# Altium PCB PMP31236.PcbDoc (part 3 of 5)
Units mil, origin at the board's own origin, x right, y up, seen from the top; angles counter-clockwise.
Board outline 6425 x 5322.16 mil, 6 copper layers (Top Layer, Power / GND 1, Signal Layer 1, Signal Layer 2, Power / GND 2, Bottom Layer), stack 78.712 mil thick; 732 components, 346 nets, 1735 pads, 719 vias.
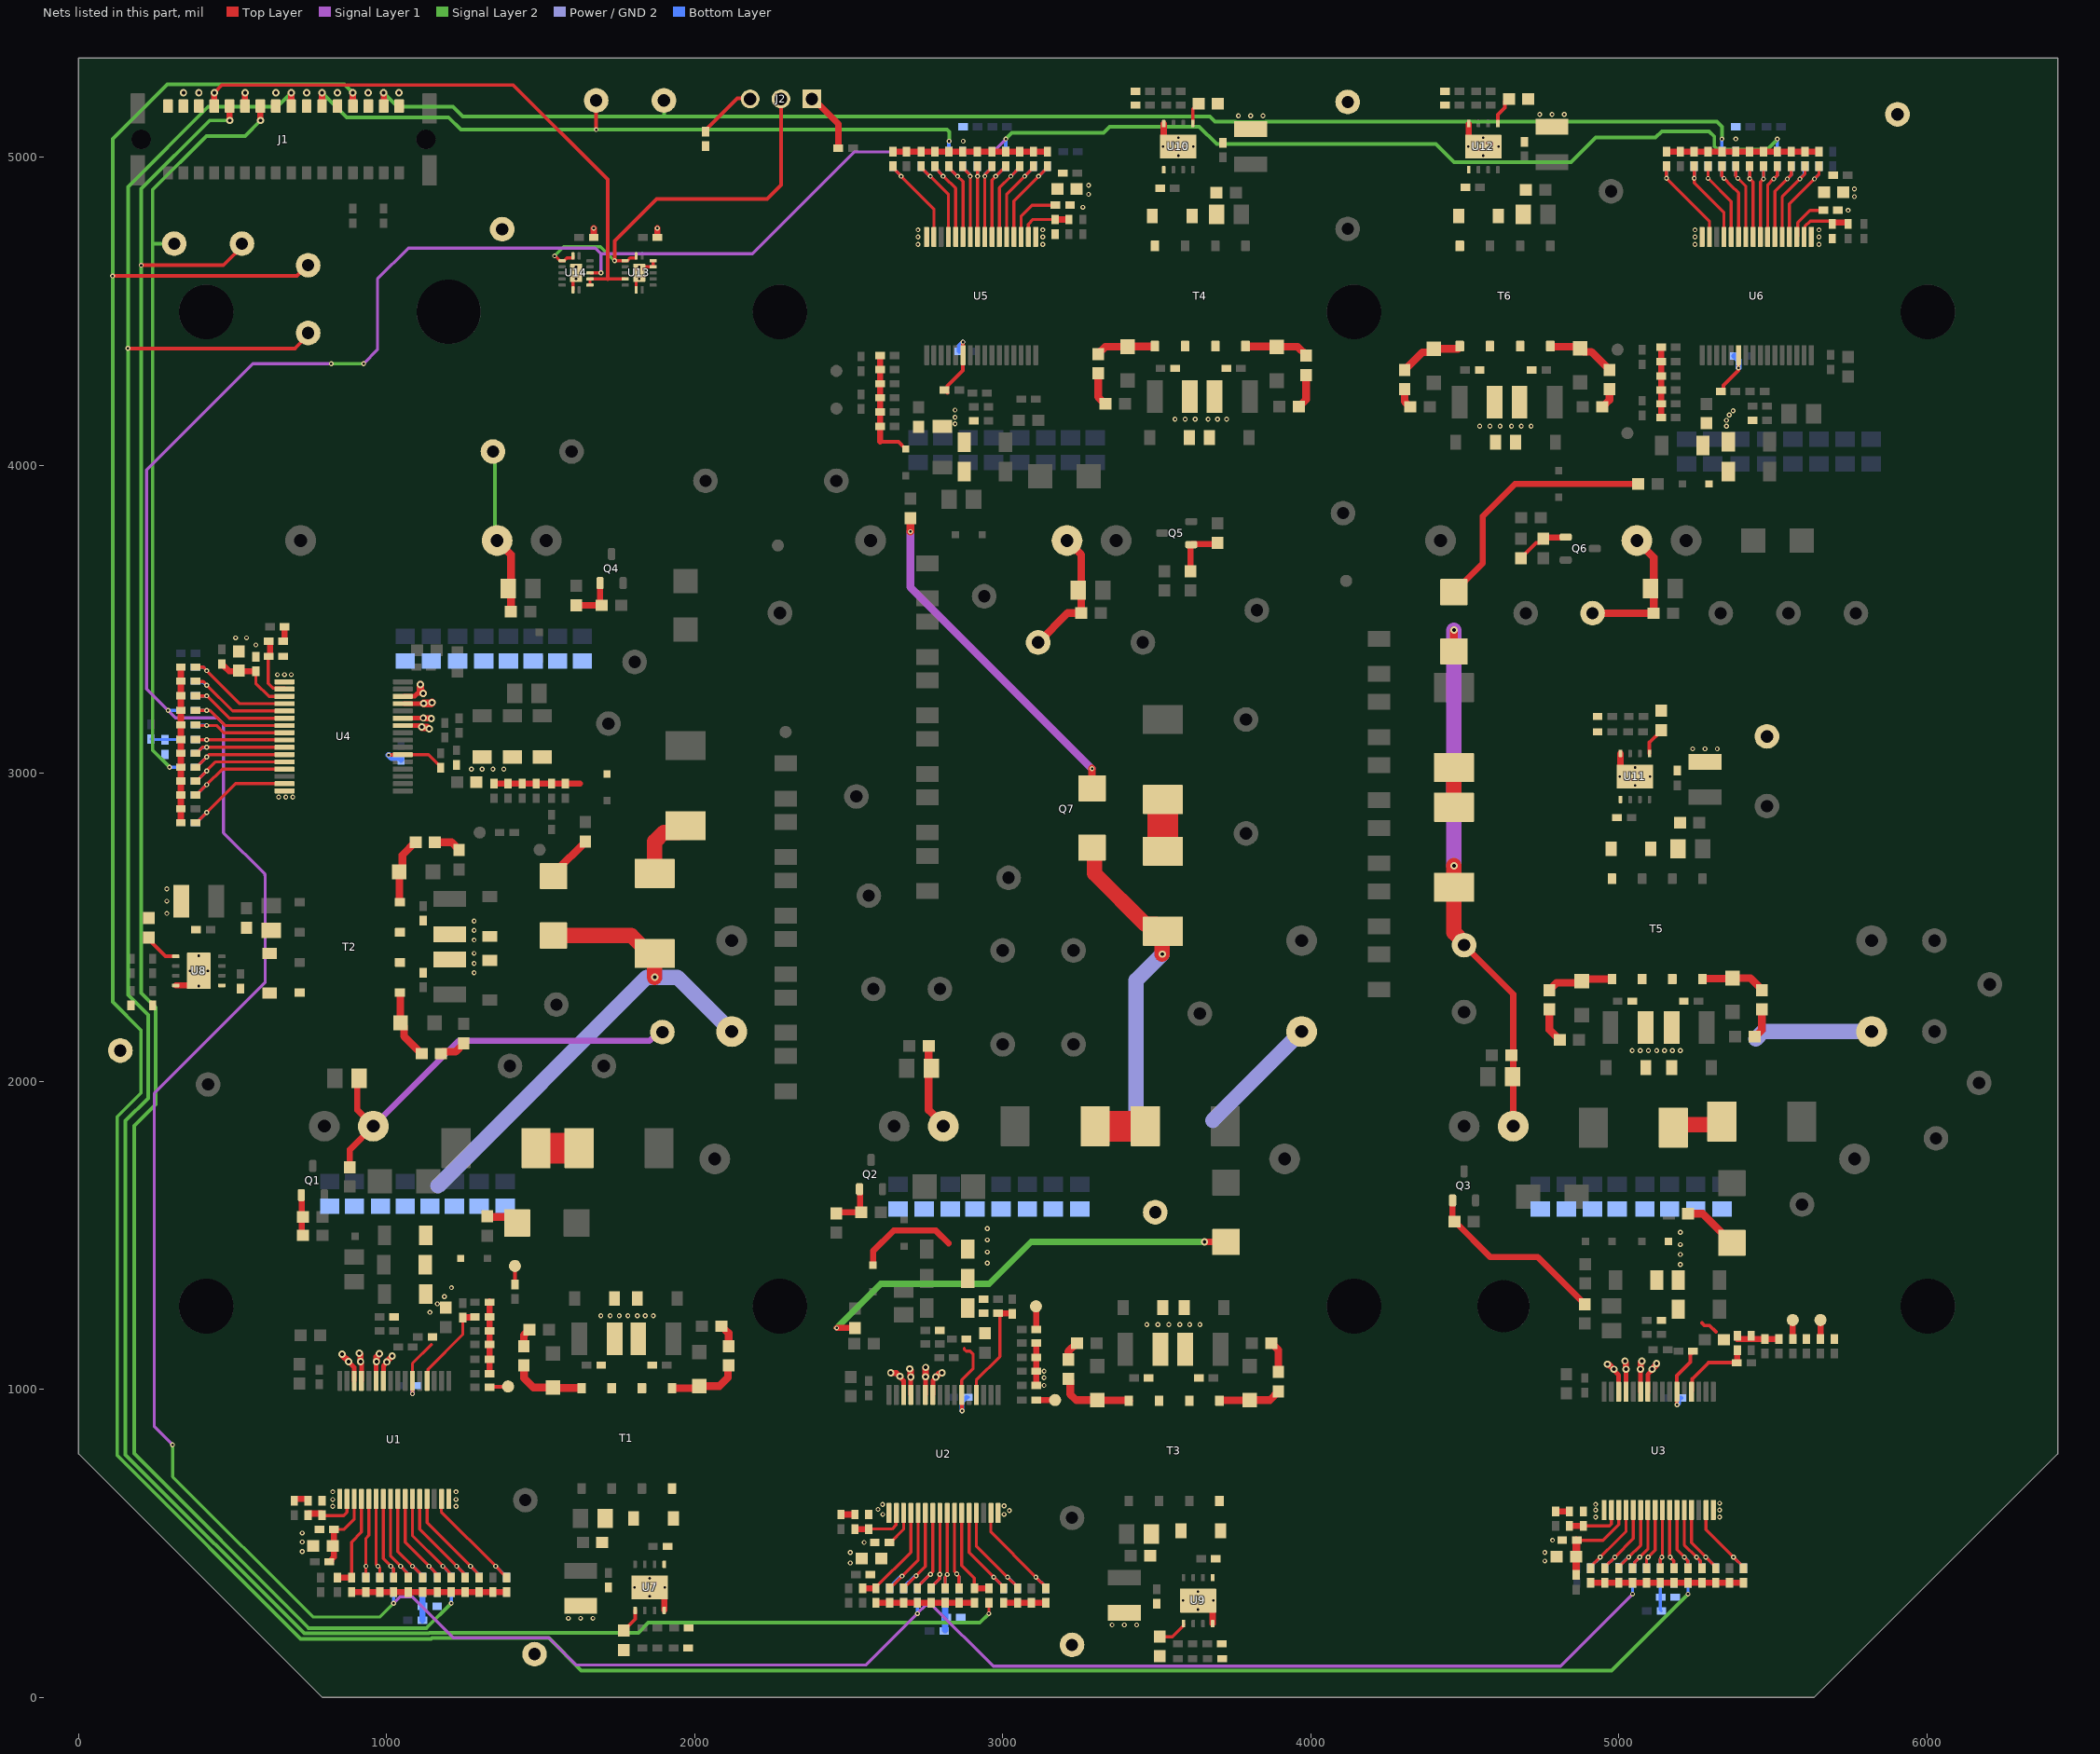
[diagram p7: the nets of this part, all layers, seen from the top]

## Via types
v1: diameter 15.75, hole 7.87, Top Layer to Bottom Layer, tented both sides, 599 vias
v2: diameter 23.62, hole 11.81, Top Layer to Bottom Layer, tented both sides, 92 vias
v3: diameter 19.68, hole 7.87, Top Layer to Bottom Layer, tented both sides, 28 vias

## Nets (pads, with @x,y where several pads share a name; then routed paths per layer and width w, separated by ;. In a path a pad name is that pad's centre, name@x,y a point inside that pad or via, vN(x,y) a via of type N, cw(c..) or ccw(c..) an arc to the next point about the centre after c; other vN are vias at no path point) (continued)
GD2: R18.1 R56.1 R94.1 R130.1 R173.1 R216.1 U14.11 | length 15373.5
  Top Layer w10: U14.11@1660,4625 v1(1695.56,4625)
  Signal Layer 1 w10: v1(304.72,819.93) 245,879.65 245,1960.01 605.35,2320.37 605.35,2667.18 604.33,2668.2 604.33,2672.7 470,2807.03 470,3160 450.04,3179.96 314.45,3179.96 v1(290.22,3204.19) 220,3274.41 220,3985 565,4330 v1(820,4330) ; v1(925,4330) 970,4375 970,4605 1070,4705 1677.67,4705 1695.56,4687.11 ; v1(1022.51,305) 1043.73,326.22 1082.1,326.22 1215.23,193.08 1525.43,193.08 1613.51,105 2556.67,105 v1(2723.05,271.38) 2723.05,272.93 2748.43,298.31 2771.69,298.31 2969.23,100.77 4810.77,100.77 v1(5045,335) ; v1(1695.56,4625) 1695.56,4687.11 ; v1(3010,5060) 2967.85,5017.85 2517.85,5017.85 2187.11,4687.11 1695.56,4687.11
  Signal Layer 2 w10: v1(304.72,819.93) 304.72,716.03 760,260.75 978.26,260.75 v1(1022.51,305) ; v1(820,4330) v1(925,4330)
  Signal Layer 2 w12: v1(3010,5060) 3030,5080 3327.06,5080 3347.06,5100 3637.9,5100 3694.73,5043.17 4405.76,5043.17 4464.82,4984.12 4845.17,4984.12 4925.18,5064.13 5119.13,5064.13 5140,5085 5292.97,5085 5310.5,5067.47 5310.5,5036.55 5321.41,5025.65 5481.66,5025.65 5515,5058.99 v1(5515,5060)
  Bottom Layer w10: v1(290.22,3204.19) 290.37,3204.34 331.23,3204.34 R130.1@331.38,3204.49 ; v1(1022.51,305) R18.1@1022.51,342.13 ; v1(2723.05,271.38) R56.1@2723.05,306.5 ; v1(5045,335) R94.1@5045,371.38 ; R216.1@5515,5018.62 v1(5515,5060)
  Bottom Layer w12: R173.1@3010,5018.62 v1(3010,5060)
GD_WEAK: J1.a4 U13.5 U14.9 U14.10 | length 1915.2
  Top Layer w10: U14.9@1660,4585.63 U14.10@1660,4605.31 1717.22,4605.31 U13.5@1774.45,4605.31
  Top Layer w12: v2(440,5210) 465,5235 1410.56,5235 1717.22,4928.34 1717.22,4605.31
  Top Layer w20: J1.a4@440,5166.54 v2(440,5210)
GND: C1.2 C2.1 C4.1 C5.1 C6.1 C7.1 C15.2 C16.2 C17.2 C18.2 C19.2 C20.2 C21.2 C22.2 C23.2 C31.2 C32.1 C34.1 C35.1 C36.1 C37.1 C45.2 C46.2 C47.2 C48.2 C49.2 C50.2 C51.2 C52.2 C53.2 C61.2 C62.1 C64.1 C65.1 C66.1 C67.1 C75.2 C76.2 C77.2 C78.2 C79.2 C80.2 C81.2 C82.2 C83.2 C91.2 C92.1 C94.1 C95.1 C96.1 C97.1 C105.2 C106.2 C107.2 C108.2 C109.2 C110.2 C111.2 C112.2 C113.2 C121.2 C122.1 C124.1 C125.1 C126.1 C127.1 C135.2 C136.2 C137.2 C138.2 C139.2 C140.2 C141.2 C142.2 C143.2 C151.2 C152.1 C154.1 C155.1 C156.1 C157.1 C165.2 C166.2 C167.2 C168.2 C169.2 C170.2 C171.2 C172.2 C173.2 C184.2 C185.2 C190.2 C194.2 C195.2 C200.2 C204.2 C205.2 C210.2 C214.2 C215.2 C220.2 C224.2 C225.2 C230.2 C234.2 C235.2 C240.2 C241.1 C242.1 J1.a1 J1.a2 J1.a3 J1.a6 J1.a8 J1.a10 J1.a12 J1.a14 J1.a16 R7.1 R30.1 R45.1 R68.1 R83.1 R106.1 R121.1 R144.1 R164.1 R187.1 R207.1 R230.1 R250.1 R251.1 R258.1 R259.1 R266.1 R267.1 R274.1 R275.1 R282.1 R283.1 R290.1 R291.1 R293.1 TP11.1 TP66.1 TP68.1 TP70.1 TP72.1 TP74.1 TP76.1 U1.1 U1.16 U2.1 U2.16 U3.1 U3.16 U4.1 U4.16 U5.1 U5.16 U6.1 U6.16 U7.8 U7.9@1853.72,356.93 U8.8 U8.9@390,2358.62 U9.8 U9.9@3634.37,313.94 U10.8 U10.9@3570,5035 U11.8 U11.9@5052.76,2989.8 U12.8 U12.9@4560.28,5035 U13.7 U13.12 U13.13 U13.15 U14.7 U14.15 | length 3740.6
  Top Layer w10: U14.7@1604.88,4569.88 1604.88,4615.16 U14.15@1614.72,4625 ; U13.7@1809.88,4569.88 1809.88,4600.47 1814.72,4605.31 v3(1819.72,4605.31) ; v3(1819.72,4644.69) U13.12@1865,4644.69 U13.13@1865,4664.37 ; R293.1@2035,5041.38 2035,5037.44 R293.1@2041.81,5030.63 ; v1@2595.23,609.58 v1(2595.23,610) ; v1(2610.61,593.78) v1@2610.61,594.2
  Top Layer w20: U8.8@315.2,2311.38 315.27,2311.45 361.02,2311.45 390,2340.42 U8.9@390,2358.62 ; C107.2@331.38,2840 C105.2@331.38,2975 C94.1@331.38,3020 C95.1@331.38,3065 C112.2@331.38,3251.73 C96.1@331.38,3345 ; J1.a6@540,5166.54 v2(540,5210) ; C6.1@886.06,342.13 1117,342.13 1209.47,342.13 1344.47,342.13 C17.2@1389.47,342.13 ; C242.1@1672.24,4740 v1(1672.24,4770) ; U7.9@1858.72,356.93 U7.9@1876.92,356.93 ; C241.1@1878.62,4740 v1(1878.62,4770) ; U7.8@1900.9,282.19 U7.9@1900.9,327.95 ; C36.1@2588.62,306.38 C52.2@2678.05,306.38 C35.1@2858.05,306.38 C34.1@2908.05,306.38 ; C137.2@2643.15,5018.62 C136.2@2687.76,5018.62 C124.1@2825,5018.62 C125.1@2870,5018.62 C142.2@3055,5018.62 C126.1@3145,5018.62 ; C45.2@3003.05,306.38 C48.2@3048.05,306.38 C46.2@3092.97,306.38 C47.2@3140.22,306.38 ; U10.8@3522.76,5109.8 3522.82,5109.73 3522.82,5063.98 3551.8,5035 U10.9@3570,5035 ; U9.9@3634.37,313.94 3652.57,313.94 3681.55,284.96 3681.55,239.2 U9.8@3681.61,239.13 ; U12.9@4513.03,5036.97 U12.8@4513.03,5109.8 ; C66.1@4908.35,371.38 C81.2@4955,371.38 C82.2@5000,371.38 C83.2@5045,371.38 C79.2@5090,371.38 C80.2@5135,371.38 C75.2@5270,371.38 C78.2@5315,371.38 C76.2@5360,371.38 C77.2@5405,371.38 ; U11.9@5005.58,3018.78 U11.8@5005.58,3064.54 ; C167.2@5155,5018.62 C168.2@5245,5018.62 C154.1@5335,5018.62 C155.1@5380,5018.62 C169.2@5470,5018.62 C171.2@5605,5018.62 C156.1@5650,5018.62
  other v1: 3355,235 3395,235 3435,235 1589.47,256.38 1629.47,256.38 1669.47,256.38 2505,436.03 4760,442.49 2505,469.88 4760,470 725.43,472.93 2550,502.87 725.43,504.17 4785,510 725.43,533.27 4925,585 5327.56,585 3004.61,593.78 3021.63,606.42 4925,608.19 5327.56,608.19 824.92,620 1225,620 3004.61,621.24 2609.98,625.92 4925,626.44 5327.56,630 824.92,642.35 1225,642.35 824.92,667.3 1225,667.3 286.22,2545 286.22,2585 286.22,2625 649.29,2923.07 672.17,2923.07 695,2923.07 5240,3079.54 5280,3079.54 5320,3079.54 645,3320.51 668.07,3320.51 690,3320.51 575,3417.09 509.02,3440 545,3440 2725,4717.8 3130,4717.8 5247.54,4717.8 5650,4717.8 2725,4741.93 3130,4741.93 5247.54,4741.93 5650,4741.93 2725,4765 3130,4765 5247.54,4765 5650,4765 5745,4828.31 3260,4838.13 5765.29,4872.67 3278.79,4880.12 5765.29,4897.83 3278.79,4910 2871.63,5052.54 5380,5060 3765,5134.99 3805,5134.99 3845,5134.99 4743.5,5139.73 4783.5,5139.73 4823.5,5139.73
  other v2: 340,5210 390,5210 640,5210 740,5210 840,5210 940,5210 1040,5210
  other v3: 3634.37,284.8 3585.16,313.94 3683.58,313.94 1853.72,327.8 3634.37,343.07 1804.51,356.93 1902.93,356.93 1853.72,386.06 390,2309.41 360.87,2358.62 419.13,2358.62 390,2407.83 5052.76,2960.67 5003.54,2989.8 5101.97,2989.8 5052.76,3018.94 1614.72,4605.31 1614.72,4644.69 3570,5005.87 4560.28,5005.87 3520.79,5035 3619.21,5035 4511.06,5035 4609.49,5035 3570,5064.13 4560.28,5064.13
GND2H_U: C3.2 C10.2 C11.2 C12.2 C13.2 C14.2 C24.2 C25.2 C28.1 C29.1 C30.1 C182.2 C183.2 C187.1 C188.1 D2.2 D19.1 D22.1 D38.2 D40.1 J15.1 J24.1 Q7.E1 Q7.T2 R25.1 R36.1 R37.1 R38.1 T1.6 T1.7 TP8.1 U1.22 | length 3586.3
  Top Layer w10: U1.22@1083.52,1027.68 1083.52,1083.84 1144.68,1145
  Top Layer w12: v1(1083.52,985.35) U1.22@1083.52,1027.68
  Top Layer w20: R25.1@880.46,1721.44 880.46,1778.3 J15.1@956.69,1854.53 904.65,1906.57 C11.2@904.65,2000 ; R38.1@1333.62,1050.63 C14.2@1333.62,1097.84 C13.2@1333.62,1145.87 R36.1@1333.62,1285
  Top Layer w50: D19.1@1541.56,2473.54 1793.82,2473.54 1852.28,2415.08 D22.1@1870,2415.08 v2(1870,2337.97)
  Signal Layer 1 w20: J15.1@956.69,1854.53 1233.54,2131.37 1853.28,2131.37 1881.91,2160 TP8.1@1895,2160 ; J24.1@2119.27,2160.81 J24.1@2120.08,2161.61
  Power / GND 2 w50: 1166.38,1660.59 1843.76,2337.97 v2(1870,2337.97) 1943.72,2337.97 J24.1@2120.08,2161.61
  Bottom Layer w12: C3.2@1083.52,1015.12 C3.2@1085.25,1016.85
  Bottom Layer w15: v1(1083.52,985.35) C3.2@1083.52,1015.12
  other v1: 1695.18,1238.7 1725.45,1238.7 1755,1238.7 1782.97,1238.7 1813.5,1238.7 1839.51,1238.7 1865.47,1238.7 1140,1250 1164.47,1277.32 1187.34,1301.01 1210.45,1330
GND2H_V: C33.2 C40.2 C41.2 C42.2 C43.2 C44.2 C54.2 C55.2 C58.1 C59.1 C60.1 C202.2 C203.2 C207.1 C208.1 D8.2 D25.1 D28.1 D48.2 D50.1 J10.1 J18.1 Q7.E3 Q7.T4 R63.1 R74.1 R75.1 R76.1 T3.6 T3.7 TP19.1 U2.22 | length 2456.7
  Top Layer w10: U2.22@2867.11,982.05 2867.11,1029.53 2903.74,1066.16 2903.74,1114.6 2894.54,1123.8 2881.81,1123.8 2875,1130.61 2875,1133.03
  Top Layer w12: U2.22@2867.11,982.05 2867.65,981.51 2867.65,930.54 v1(2868.19,930)
  Top Layer w20: D8.2@2578.86,1405.12 2578.86,1448.41 2645.79,1515.35 2783.25,1515.35 2824.43,1474.16 ; R76.1@3108.62,1012.52 R75.1@3108.62,1150
  Top Layer w25: R63.1@2759.55,2115 2759.55,1906.42 2807.09,1858.88 J10.1@2807.09,1854.53
  Top Layer w50: D25.1@3290,2758.54 3298.1,2750.44 3298.1,2674.81 3463.43,2509.49 3497.76,2509.49 D28.1@3520,2487.24 3517.76,2485 v2(3517.76,2412.98)
  Power / GND 2 w50: 3432.46,1905 3432.46,2327.69 v2(3517.76,2412.98) ; 3681.81,1872.95 J18.1@3970.47,2161.61
  Bottom Layer w12: C33.2@2882.58,974.06 C33.2@2886.52,974.06
  Bottom Layer w15: v1(2868.19,930) 2868.19,959.66 C33.2@2882.58,974.06
  other v1: 3134.21,1012.52 3134.21,1037.31 3134.21,1058.84 3467.99,1210 3503.8,1210 3539.38,1210 3575,1210 3607.23,1210 3640.47,1210 2950,1410 2950,1445.83 2950,1485 2950,1521.68
GND2H_W: C63.2 C70.2 C71.2 C72.2 C73.2 C74.2 C84.2 C85.2 C88.1 C89.1 C90.1 C222.2 C223.2 C227.1 C228.1 D14.2 D31.1 D34.1 D58.2 D60.1 J12.1 J19.1 Q7.E5 Q7.T6 R101.1 R112.1 R113.1 R114.1 T5.6 T5.7 TP29.1 U3.22 | length 2561.5
  Top Layer w12: v1(5189.37,949.72) 5189.21,949.88 5189.21,991.89 U3.22@5189.06,992.05 5189.06,1044.97 5232.9,1088.81 5232.9,1112.81 5238.71,1118.62 C85.2@5241.3,1118.62 ; 5270,1215.63 5278.5,1207.13 5294.59,1207.13 5315.19,1186.53 5315.19,1186.05
  Top Layer w20: TP29.1@4498.03,2442.17 4657.48,2282.72 J12.1@4657.48,1854.53 ; C72.2@5385,1163.62 C73.2@5475,1163.62 R113.1@5520,1163.62
  Top Layer w25: D31.1@4465,3395.71 v2(4465,3465)
  Top Layer w50: v2(4465,2699.96) D34.1@4465,2630.08 4465,2483.31 4498.03,2450.28 TP29.1@4498.03,2442.17
  Signal Layer 1 w50: v2(4465,2699.96) v2(4465,3465)
  Power / GND 2 w50: 5444.45,2137 5469.06,2161.61 J19.1@5820.87,2161.61
  Bottom Layer w15: v1(5189.37,949.72) 5189.37,949.93 5194.78,955.34 5194.78,967.91 5199.1,972.22 C63.2@5203.03,972.22
  other v1: 5200.13,1405.36 5200.13,1437.68 5200.22,1470 5200.13,1509.76 5043.62,2100 5070.09,2100 5096.38,2100 5123.31,2100 5148.83,2100 5173.98,2100 5200.13,2100
GND2L_U: C93.2 C100.2 C101.2 C102.2 C103.2 C104.2 C114.2 C115.2 C118.1 C119.1 C120.1 C192.2 C193.2 C197.1 C198.1 D20.2 D43.2 D45.1 J11.1 Q7.E2 R138.1 R149.1 R150.1 R157.1 T2.6 T2.7 TP40.1 U4.22 | length 1061.4
  Top Layer w10: U4.22@1056.93,3060.94 1135.75,3060.94 1175,3021.69 C115.2@1175,3017.76
  Top Layer w12: v1(1006.36,3059.58) 1007.04,3060.26 1051.25,3060.26 U4.22@1051.93,3060.94 U4.22@1056.93,3060.94
  Top Layer w20: C102.2@1348.75,2966.38 C102.2@1348.75,2966.38 1627.46,2966.42 1627.5,2966.46
  Top Layer w25: J11.1@1358.27,3756.1 1403.5,3710.87 R138.1@1403.5,3525
  Signal Layer 2 w12: TP40.1@1345,4045 1351.63,4038.37 1351.63,3762.74 J11.1@1358.27,3756.1
  Bottom Layer w20: v1(1006.36,3059.58) 1015.85,3050.1 1044.92,3050.1 1046.73,3048.29 C93.2@1046.73,3044.35
  other v1: 1283.55,2352.5 1283.55,2382.83 1283.55,2415.49 1283.55,2458.83 1283.55,2490 1283.55,2520.27 1275,3013.7 1310,3013.7 1345,3013.7 1380,3013.7
GND2L_V: C123.2 C130.2 C131.2 C132.2 C133.2 C134.2 C144.2 C145.2 C148.1 C149.1 C150.1 C212.2 C213.2 C217.1 C218.1 D26.2 D53.2 D55.1 J22.1 Q7.E4 R181.1 R192.1 R193.1 R200.1 T4.6 T4.7 TP51.1 U5.22 | length 1036.5
  Top Layer w12: 2601.38,4076.93 2661.38,4076.93 D26.2@2685,4053.31 ; C145.2@2811.38,4245 C145.2@2815.32,4245 ; C145.2@2821.13,4235.25 2821.13,4239.19 C145.2@2815.32,4245 ; v1(2870.94,4400.39) U5.22@2870.94,4358.07 2870.94,4307.59 2821.13,4257.77 2821.13,4250.81 C145.2@2815.32,4245
  Top Layer w20: 2601.38,4076.93 R200.1@2601.38,4126.93 R192.1@2601.38,4220 R193.1@2601.38,4356.5
  Top Layer w25: TP51.1@3115.04,3425 3210.94,3520.91 R181.1@3254.78,3520.91 3254.78,3709.98 J22.1@3208.66,3756.1
  Bottom Layer w15: C123.2@2859.09,4370.02 2859.09,4388.53 v1(2870.94,4400.39)
  other v1: 2845,4135 3559.25,4150 3592.28,4150 3624.92,4150 3666.75,4150 3697.17,4150 3727.05,4150 2845,4156.46 2845,4179.65
GND2L_W: C153.2 C160.2 C161.2 C162.2 C163.2 C164.2 C174.2 C175.2 C178.1 C179.1 C180.1 C232.2 C233.2 C237.1 C238.1 D32.2 D63.2 D65.1 J7.1 Q7.E6 R224.1 R235.1 R236.1 R243.1 T6.6 T6.7 TP62.1 U6.22 | length 874.7
  Top Layer w10: C175.2@5331.69,4240 5333.53,4240 C175.2@5340.34,4246.81
  Top Layer w12: C175.2@5340.34,4246.81 5340.34,4260.13 5388.06,4307.85 5388.06,4316.09 v1(5388.78,4316.81) ; v1@5388.94,4316.81 U6.22@5388.94,4358.07
  Top Layer w20: C162.2@5137.87,4155 C163.2@5137.87,4290.19 C164.2@5137.87,4337.19 R236.1@5137.87,4384.06
  Top Layer w25: TP62.1@4915,3520 R224.1@5113.5,3520 5113.5,3701.65 J7.1@5059.06,3756.1
  Bottom Layer w20: C153.2@5376.2,4355 5380.14,4355 5381.95,4353.19 5381.95,4349.25 5388.78,4342.42 v1(5388.78,4316.81)
  other v1: 4548.62,4127.47 4581.97,4127.47 4615,4127.47 4651.79,4127.47 4683.5,4127.47 4715.47,4127.47 5350,4127.47 5350,4146.46 5358.96,4163.63 5371.32,4177.26
HS_DO_PWM_U: J1.a5 R5.1 TP5.1 | length 6280.8
  Top Layer w12: v1(202.99,4650) 470,4650 TP5.1@540,4720
  Top Layer w20: v2(490,5120) J1.a5@490,5166.54
  Signal Layer 2 w12: v2(490,5120) 425,5120 202.99,4897.99 v1(202.99,4650) 202.99,2287.01 250,2240 250,1925 180,1855 180,791.5 746.5,225 1129.47,225 v1(1209.47,305)
  Bottom Layer w10: v1(1209.47,305) R5.1@1209.47,342.13
HS_DO_PWM_V: J1.a9 R43.1 TP16.1 | length 8592.3
  Top Layer w10: v1(2955,271.38) R43.1@2955,306.38
  Top Layer w12: v1(160,4380) 701.54,4380 TP16.1@751.54,4430
  Top Layer w20: J1.a9@690,5166.54 v2(690,5210)
  Signal Layer 2 w12: v2(690,5210) 645,5165 420,5165 160,4905 v1(160,4380) 160,2280 225,2215 225,1945 151.57,1871.57 151.57,787.61 732.09,207.09 1136.89,207.09 1139.6,209.81 1817.03,209.81 1849.34,242.13 2925.75,242.13 v1(2955,271.38)
HS_DO_PWM_W: J1.a13 R81.1 TP26.1 | length 11433.2
  Top Layer w12: v1(110,4615) 707.92,4615 TP26.1@742.92,4650
  Top Layer w20: v2(889.84,5210) 889.92,5209.92 889.92,5166.61 J1.a13@890,5166.54
  Signal Layer 1 w12: TP26.1@742.92,4650 TP26.1@745,4650
  Signal Layer 2 w12: v2(889.84,5210) 862.42,5237.42 287.42,5237.42 110,5060 v1(110,4615) 110,2257.85 202.09,2165.76 202.09,1962.09 125,1885 125,785 720.81,189.19 1144.3,189.19 1147.02,191.91 1526.61,191.91 1631.4,87.11 4977.11,87.11 v1(5225,335)
  Bottom Layer w10: v1(5225,335) R81.1@5225,371.38
LS_DO_PWM_U: J1.a7 R119.1 TP36.1 | length 2498.9
  Top Layer w20: v2(590,5120) J1.a7@590,5166.54
  Signal Layer 2 w12: 240,4720 TP36.1@315,4720 ; v1(295,3020) 240,3075 240,4895 415,5070 540,5070 v2(590,5120)
  Bottom Layer w10: v1(295,3020) R119.1@331.38,3020
LS_DO_PWM_V: J1.a11 R162.1 TP47.1 | length 2291.8
  Top Layer w12: v1(1680,5090.22) TP47.1@1680,5185
  Top Layer w20: J1.a11@790,5166.54 v2(790,5210)
  Signal Layer 2 w12: v2(790,5210) 870,5130 1200.79,5130 1240.57,5090.22 2818.85,5090.22 2826.16,5082.91 v1(2826.16,5052.54)
  Bottom Layer w12: R162.1@2825,5018.62 2825.58,5019.2 2825.58,5051.96 v1(2826.16,5052.54)
LS_DO_PWM_W: J1.a15 R205.1 TP58.1 | length 4568.3
  Top Layer w20: J1.a15@990,5166.54 v2(990,5210)
  Signal Layer 2 w12: v2(990,5210) 1035,5165 1215,5165 1247.5,5132.5 1900,5132.5 ; TP58.1@1900,5185 1900,5132.5 ; v1(5335,5060) 5335,5100 5319.29,5115.71 3853.69,5115.71 3853.19,5115.21 3756.81,5115.21 3756.31,5115.71 3689.07,5115.71 3672.27,5132.5 1900,5132.5
  Bottom Layer w10: R205.1@5335,5018.62 v1(5335,5060)
NetC1_1: C1.1 C2.2 R1.2 U1.3 | length 258
  Top Layer w10: C2.2@828.62,545 860,545 894.55,579.55 U1.3@894.55,643.82
  Top Layer w20: R1.2@813.62,440 817.56,440 819.37,441.81 819.37,445.75 828.62,455 C2.2@828.62,545
NetC4_2: C4.2 R5.2 U1.11 | length 356.3
  Top Layer w10: U1.11@1083.52,643.82 1083.52,524.25 v1(1182.09,425.68) C4.2@1214.47,393.31 ; C4.2@1209.47,389.37 C4.2@1209.47,393.31
  Bottom Layer w10: v1(1182.09,425.68) 1202.66,405.12 1202.66,396.18 R5.2@1209.47,389.37
NetC5_2: C5.2 R7.2 U1.10 | length 347.5
  Top Layer w10: U1.10@1059.9,643.82 1059.9,502.87 v1(1137.09,425.68) C5.2@1169.47,393.31 ; C5.2@1164.47,389.37 C5.2@1164.47,393.31
  Bottom Layer w10: v1(1137.09,425.68) 1157.66,405.12 1157.66,396.18 R7.2@1164.47,389.37
NetC6_2: C6.2 R8.2 U1.4 | length 313.8
  Top Layer w10: C6.2@886.06,389.37 886.06,504.17 918.17,536.29 U1.4@918.17,643.82
  Top Layer w20: R8.2@840,388.62 C6.2@886.06,388.62
NetC7_2: C7.2 R11.2 U1.2 | length 176
  Top Layer w10: C7.2@790,596.38 796.38,590 860,590 870.93,600.93 U1.2@870.93,643.82
  Top Layer w20: R11.2@745,596.38 C7.2@790,596.38
NetC12_1: C12.1 R33.1 U1.20 | length 293.5
  Top Layer w10: U1.20@1130.77,1027.68 1133.84,1030.75 1133.84,1064.74 1246.68,1177.58 R33.1@1246.68,1232.34 R33.1@1248.01,1233.67
  Top Layer w20: R33.1@1248.01,1233.67 1285.05,1233.67 C12.1@1286.38,1235
NetC15_1: C15.1 R28.2 U1.12 | length 365.2
  Top Layer w10: U1.12@1107.15,643.82 1107.15,545.63 v1(1227.09,425.68) C15.1@1259.47,393.31 ; C15.1@1254.47,389.37 C15.1@1254.47,393.31
  Bottom Layer w10: v1(1227.09,425.68) 1247.66,405.12 1247.66,396.18 R28.2@1254.47,389.37
NetC17_1: C17.1 R34.2 U1.15 | length 400.9
  Top Layer w10: U1.15@1178.01,643.82 1177.15,642.95 1177.15,602.32 v1(1353.79,425.68) C17.1@1384.41,395.06 ; C17.1@1382.66,400.12 1389.47,393.31 C17.1@1389.47,389.37
  Bottom Layer w10: v1(1353.79,425.68) 1379.35,400.12 1382.66,400.12 1389.47,393.31 R34.2@1389.47,390
NetC18_1: C18.1 R35.2 U1.13 | length 374.1
  Top Layer w10: U1.13@1130.77,643.82 1130.77,567.01 v1(1272.09,425.68) C18.1@1304.47,393.31 ; C18.1@1299.47,389.37 C18.1@1299.47,393.31
  Bottom Layer w10: v1(1272.09,425.68) 1292.66,405.12 1292.66,396.18 R35.2@1299.47,389.37
NetC19_1: C19.1 R22.2 U1.8 | length 331.7
  Top Layer w10: U1.8@1012.66,643.82 1012.66,458.03 v1(1045,425.68) 1067.94,402.74 C19.1@1067.94,391.18 ; C19.1@1062.94,396.18 C19.1@1067.94,391.18 ; C19.1@1069.76,389.37 C19.1@1067.94,391.18
  Bottom Layer w10: v1(1045,425.68) 1062.94,407.74 1062.94,396.18 R22.2@1069.76,389.37
NetC20_1: C20.1 R26.2 U1.9 | length 339.4
  Top Layer w10: U1.9@1036.28,643.82 1036.28,472.93 v1(1083.52,425.68) 1084.62,425.68 1117,393.31 C20.1@1117,389.37
  Bottom Layer w10: v1(1083.52,425.68) 1084.62,425.68 1117,393.31 R26.2@1117,389.37
NetC21_1: C21.1 R14.2 U1.5 | length 294.6
  Top Layer w10: C21.1@932.51,389.37 v1(932.51,425.68) 932.51,516.34 941.79,525.62 U1.5@941.79,643.82
  Bottom Layer w10: R14.2@932.51,389.37 v1(932.51,425.68)
NetC22_1: C22.1 R15.2 U1.6 | length 298.3
  Top Layer w10: U1.6@965.41,643.82 965.41,431.73 v1(971.46,425.68) 977.51,419.63 C22.1@977.51,389.37
  Bottom Layer w10: v1(971.46,425.68) 971.46,424.13 977.51,418.08 R15.2@977.51,389.37
NetC23_1: C23.1 R18.2 U1.7 | length 308.4
  Top Layer w10: U1.7@989.04,643.82 989.04,450 v1(1013.35,425.68) 1022.51,416.52 C23.1@1022.51,389.37
  Bottom Layer w10: v1(1013.35,425.68) 1022.51,416.52 R18.2@1022.51,389.37
NetC31_1: C31.1 C32.2 R39.2 U2.3 | length 113.1
  Top Layer w10: C32.2@2635.73,502.68 2678.13,545.08 U2.3@2678.13,598.19
NetC34_2: C34.2 R43.2 U2.11 | length 312.3
  Top Layer w10: U2.11@2867.11,598.19 2867.11,427.8 2908.05,386.85 2908.05,353.74 C34.2@2908.17,353.62 ; R43.2@2955,353.62 R43.2@2955,357.56
  Top Layer w20: C34.2@2908.17,353.62 R43.2@2955,353.62
NetC35_2: C35.2 R45.2 U2.10 | length 300.7
  Top Layer w10: U2.10@2843.49,598.19 2843.49,408.11 2858.05,393.54 C35.2@2858.05,353.62
  Bottom Layer w10: v1(2850.77,400.83) 2850.77,399.27 2858.05,391.99 R45.2@2858.05,353.74
NetC36_2: C36.2 R46.2 U2.4 | length 335
  Top Layer w10: C36.2@2588.62,353.62 2588.62,357.56 2701.75,470.69 U2.4@2701.75,598.19
  Top Layer w20: R46.2@2545,353.62 C36.2@2588.62,353.62
NetC37_2: C37.2 R49.2 U2.2 | length 193.2
  Top Layer w10: 2550,546.38 2640.62,546.38 2653.15,558.91 2653.15,596.83 U2.2@2654.51,598.19
  Top Layer w20: R49.2@2520,546.38 C37.2@2565,546.38
NetC42_1: C42.1 R71.1 U2.20 | length 343.1
  Top Layer w10: U2.20@2914.35,982.05 2914.35,1029.53 2991.2,1106.38 2991.2,1240.77 C42.1@2985.87,1246.11
  Top Layer w20: C42.1@2985.87,1246.11 3029.98,1246.11 R71.1@3030.63,1245.45
NetC45_1: C45.1 R66.2 U2.12 | length 340.7
  Top Layer w10: U2.12@2890.73,598.19 2890.73,469.88 v1(2970.75,389.86) 3003.05,357.56 C45.1@3003.05,353.62
  Bottom Layer w10: v1(2970.75,389.86) 2970.87,389.86 3003.05,357.68 R66.2@3003.05,353.74
NetC47_1: C47.1 R72.2 U2.15 | length 368
  Top Layer w10: U2.15@2961.6,598.19 2961.6,536.18 v1(3107.91,389.86) 3140.22,357.56 C47.1@3140.22,353.74
  Bottom Layer w10: v1(3107.91,389.86) 3108.03,389.86 3140.22,357.68 R72.2@3140.22,353.74
NetC48_1: C48.1 R73.2 U2.13 | length 349.5
  Top Layer w10: U2.13@2914.35,598.19 2914.35,491.26 v1(3015.75,389.86) 3048.05,357.56 C48.1@3048.05,353.62
  Bottom Layer w10: v1(3015.75,389.86) 3015.87,389.86 3048.05,357.68 R73.2@3048.05,353.74
NetC49_1: C49.1 R60.2 U2.8 | length 307.8
  Top Layer w10: C49.1@2768.56,358.07 2794.55,384.05 2794.55,397.68 v1(2795.65,398.78) ; v1@2796.24,398.78 U2.8@2796.24,598.19
  Bottom Layer w10: R60.2@2768.05,353.74 2768.05,357.68 2794.55,384.17 2794.55,397.68 v1(2795.65,398.78)
NetC50_1: C50.1 R64.2 U2.9 | length 294.9
  Top Layer w10: C50.1@2813.05,353.74 2813.05,390.18 2819.86,396.99 v1(2819.86,398.54) U2.9@2819.86,598.19
  Bottom Layer w10: R64.2@2813.05,353.74 2813.05,390.18 2819.86,396.99 v1(2819.86,398.54)
NetC51_1: C51.1 R52.2 U2.5 | length 343.8
  Top Layer w10: C51.1@2633.05,353.62 2633.05,357.56 2639.86,364.37 2643.8,364.37 v1(2672.97,393.54) 2725.37,445.94 U2.5@2725.37,598.19
  Bottom Layer w10: R52.2@2633.05,353.74 2633.05,357.68 2667.82,392.44 2671.87,392.44 v1(2672.97,393.54)
NetC52_1: C52.1 R53.2 U2.6 | length 336.1
  Top Layer w10: C52.1@2678.05,353.74 2678.05,357.56 2684.86,364.37 2688.68,364.37 v1(2718.84,394.53) 2749,424.68 U2.6@2749,598.19
  Bottom Layer w10: R53.2@2678.05,353.74 2678.05,357.68 2713.8,393.43 2717.74,393.43 v1(2718.84,394.53)
NetC53_1: C53.1 R56.2 U2.7 | length 324.7
  Top Layer w10: C53.1@2723.05,357.56 2764.28,398.78 v1(2765.11,398.78) 2765.11,400.34 2772.62,407.85 U2.7@2772.62,598.19
  Bottom Layer w10: R56.2@2723.05,353.74 2723.05,357.68 2764.16,398.78 v1(2765.11,398.78)
NetC61_1: C61.1 C62.2 R77.2 U3.3 | length 316.1
  Top Layer w10: C62.2@4864.27,509.35 4948.72,509.35 5000.08,560.71 U3.3@5000.08,608.19
  Top Layer w25: R77.2@4861.5,396.97 C61.1@4861.5,456.81 ; C61.1@4862.28,457.6 C62.2@4862.28,509.31
NetC64_2: C64.2 R81.2 U3.11 | length 245.8
  Top Layer w10: U3.11@5189.06,608.19 5189.06,478.94 v1(5213,455) 5224.49,443.51 5224.49,419.13 C64.2@5225,418.62
  Bottom Layer w10: v1(5213,455) 5223.79,444.21 5223.79,419.83 R81.2@5225,418.62
NetC65_2: C65.2 R83.2 U3.10 | length 237.3
  Top Layer w10: U3.10@5165.43,608.19 5165.43,456.81 v1(5167.24,455) 5178.73,443.51 5178.73,419.89 C65.2@5180,418.62
  Bottom Layer w10: v1(5167.24,455) 5178.03,444.21 5178.03,420.59 R83.2@5180,418.62
NetC66_2: C66.2 R84.2 U3.4 | length 286.8
  Top Layer w10: C66.2@4908.35,418.62 4908.35,422.56 5023.7,537.91 U3.4@5023.7,608.19
  Bottom Layer w10: R84.2@4908.35,418.62 4908.35,422.56 4940,454.21 v1(4940,455)
NetC67_2: C67.2 R87.2 U3.2 | length 184.8
  Top Layer w10: C67.2@4885,556.38 4970.6,556.4 4976.46,562.26 U3.2@4976.46,608.19
  Top Layer w20: R87.2@4840,556.38 C67.2@4885,556.38
NetC72_1: C72.1 R109.1 U3.20 | length 244.8
  Top Layer w12: U3.20@5236.3,992.05 5238.37,994.12 5238.37,1033.14 5292.23,1087 R109.1@5384.2,1087
  Top Layer w20: R109.1@5384.2,1087 5384.2,1120.58 C72.1@5385,1121.38
NetC75_1: C75.1 R104.2 U3.12 | length 256.9
  Top Layer w10: U3.12@5212.68,608.19 5212.68,494.92 v1(5252.6,455) 5265.1,442.49 5265.1,423.52 C75.1@5270,418.62
  Bottom Layer w10: v1(5252.6,455) 5263.38,444.21 5263.38,425.24 R104.2@5270,418.62
NetC77_1: C77.1 R110.2 U3.15 | length 289.7
  Top Layer w10: U3.15@5283.54,608.19 5283.54,544.02 v1(5372.56,455) 5405,422.56 C77.1@5405,418.62
  Bottom Layer w10: v1(5372.56,455) 5405,422.56 R110.2@5405,418.62
NetC78_1: C78.1 R111.2 U3.13 | length 272
  Top Layer w10: U3.13@5236.3,608.19 5236.3,501.26 v1(5282.56,455) 5315,422.56 C78.1@5315,418.62
  Bottom Layer w10: v1(5282.56,455) 5315,422.56 R111.2@5315,418.62
NetC79_1: C79.1 R98.2 U3.8 | length 240
  Top Layer w10: C79.1@5090,418.62 5090,449.37 v1(5095.63,455) 5118.19,477.56 U3.8@5118.19,608.19
  Bottom Layer w10: R98.2@5090,418.62 5090,447.81 5095.63,453.44 v1(5095.63,455)
NetC80_1: C80.1 R102.2 U3.9 | length 230.8
  Top Layer w10: C80.1@5135,418.62 5135,450 v1(5140,455) 5141.81,456.81 U3.9@5141.81,608.19
  Bottom Layer w10: R102.2@5135,418.62 5135,448.44 5140,453.44 v1(5140,455)
NetC81_1: C81.1 R90.2 U3.5 | length 277.6
  Top Layer w10: C81.1@4955,418.62 4955,422.56 v1(4987.44,455) 5047.32,514.88 U3.5@5047.32,608.19
  Bottom Layer w10: R90.2@4955,418.62 4955,422.56 v1(4987.44,455)
NetC82_1: C82.1 R91.2 U3.6 | length 268
  Top Layer w10: C82.1@5000,418.62 5000,422.56 v1(5032.44,455) 5070.94,493.5 U3.6@5070.94,608.19
  Bottom Layer w10: R91.2@5000,420.59 5000,424.53 5029.37,453.9 5031.34,453.9 v1(5032.44,455)
NetC83_1: C83.1 R94.2 U3.7 | length 256.1
  Top Layer w10: C83.1@5045,418.62 5051.81,425.43 5051.81,438.46 v1(5068.35,455) 5094.57,481.22 U3.7@5094.57,608.19
  Bottom Layer w10: R94.2@5045,418.62 5051.81,425.43 5051.81,438.46 v1(5068.35,455)
NetC91_1: C91.1 C92.2 R115.2 U4.3 | length 276.8
  Top Layer w10: C92.2@575,3331.38 575,3292.57 617.65,3249.92 U4.3@673.07,3249.92
  Top Layer w20: R115.2@464.8,3355 464.8,3351.06 466.61,3349.25 470.55,3349.25 488.43,3331.38 C92.2@575,3331.38
NetC94_2: C94.2 R119.2 U4.11 | length 362.2
  Top Layer w10: C94.2@378.62,3020 382.56,3020 v1(415.71,3053.15) 423.5,3060.94 U4.11@673.07,3060.94
  Bottom Layer w10: R119.2@378.62,3020 382.56,3020 v1(415.71,3053.15)
NetC95_2: C95.2 R121.2 U4.10 | length 347.7
  Top Layer w10: C95.2@378.62,3065 382.56,3065 402.13,3084.57 v1(415.71,3084.57) U4.10@673.07,3084.57
  Bottom Layer w10: R121.2@378.62,3065 382.56,3065 401.03,3083.47 414.61,3083.47 v1(415.71,3084.57)
NetC96_2: C96.2 R122.2 U4.4 | length 385.5
  Top Layer w10: C96.2@378.62,3345 404.21,3345 v1(415.71,3333.5) 522.91,3226.3 U4.4@673.07,3226.3
  Bottom Layer w10: R122.2@378.62,3345 404.21,3345 v1(415.71,3333.5)
NetC97_2: C97.2 R125.2 U4.2 | length 195.7
  Top Layer w10: C97.2@614.8,3373.35 614.8,3292.57 630.76,3276.61 670,3276.61 U4.2@673.07,3273.54
  Top Layer w20: C97.2@621.38,3380 R125.2@621.38,3428.82
NetC105_1: C105.1 R142.2 U4.12 | length 371
  Top Layer w10: C105.1@378.62,2975 382.56,2975 444.88,3037.32 U4.12@673.07,3037.32
  Bottom Layer w10: R142.2@378.62,2975 382.56,2975 415.42,3007.86 v1(415.71,3007.86)
NetC107_1: C107.1 R147.2 U4.15 | length 397.6
  Top Layer w10: C107.1@378.62,2840 382.56,2840 v1(415.71,2873.15) 509.02,2966.46 U4.15@673.07,2966.46
  Bottom Layer w10: R147.2@378.62,2840 382.56,2840 v1(415.71,2873.15)
NetC108_1: C108.1 R148.2 U4.13 | length 379.9
  Top Layer w10: C108.1@378.62,2930 382.56,2930 v1(415.71,2963.15) 466.26,3013.7 U4.13@673.07,3013.7
  Bottom Layer w10: R148.2@378.62,2930 382.56,2930 v1(415.71,2963.15)
NetC109_1: C109.1 R134.2 U4.8 | length 342.8
  Top Layer w10: C109.1@378.62,3157.24 380.43,3155.43 v1(415.71,3155.43) 447.09,3155.43 470.71,3131.81 U4.8@673.07,3131.81
  Bottom Layer w10: R134.2@378.62,3157.24 379.53,3156.34 414.8,3156.34 v1(415.71,3155.43)
NetC110_1: C110.1 R140.2 U4.9 | length 332.7
  Top Layer w10: C110.1@378.62,3110 379.53,3109.09 v1(415.71,3109.09) 672.17,3109.09 U4.9@673.07,3108.19
  Bottom Layer w10: R140.2@378.62,3110 379.07,3109.55 415.26,3109.55 v1(415.71,3109.09)
NetC111_1: C111.1 R128.2 U4.5 | length 377.5
  Top Layer w10: C111.1@378.62,3300 380.71,3297.91 404.21,3297.91 v1(415.71,3286.42) 499.45,3202.68 U4.5@673.07,3202.68
  Bottom Layer w10: R128.2@378.62,3300 381.56,3297.06 403.51,3297.06 414.15,3286.42 v1(415.71,3286.42)
NetC112_1: C112.1 R129.2 U4.6 | length 361.6
  Top Layer w10: C112.1@378.62,3251.73 v1(415.71,3251.73) 417.32,3251.73 490,3179.06 U4.6@673.07,3179.06
  Bottom Layer w10: R129.2@378.62,3251.73 v1(415.71,3251.73)
NetC113_1: C113.1 R130.2 U4.7 | length 351.9
  Top Layer w10: C113.1@378.62,3204.49 v1(415.71,3204.49) 425.51,3204.49 474.57,3155.43 U4.7@673.07,3155.43
  Bottom Layer w10: R130.2@378.62,3204.49 v1(415.71,3204.49)
NetC121_1: C121.1 C122.2 R158.2 U5.3 | length 194
  Top Layer w10: U5.3@3059.92,4741.93 3059.92,4809.92 3095,4845 C122.2@3171.38,4845
NetC124_2: C124.2 R162.2 U5.11 | length 292.9
  Top Layer w10: C124.2@2825,4971.38 2825,4967.44 v1(2853.62,4938.82) 2870.94,4921.5 U5.11@2870.94,4741.93
  Bottom Layer w10: R162.2@2825,4971.38 2825,4967.44 v1(2853.62,4938.82)
NetC125_2: C125.2 R164.2 U5.10 | length 282.4
  Top Layer w10: C125.2@2870,4971.38 2870,4967.44 2894.57,4942.87 v1(2894.57,4938.82) U5.10@2894.57,4741.93
  Bottom Layer w10: R164.2@2870,4971.38 2870,4967.44 2893.47,4943.97 2893.47,4939.92 v1(2894.57,4938.82)
NetC126_2: C126.2 R165.2 U5.4 | length 318.9
  Top Layer w10: U5.4@3036.3,4741.93 3036.3,4858.74 v1(3116.38,4938.82) 3145,4967.44 C126.2@3145,4971.38
  Bottom Layer w10: v1(3116.38,4938.82) 3145,4967.44 R165.2@3145,4971.38
NetC127_2: C127.2 R168.2 U5.2 | length 199.7
  Top Layer w10: U5.2@3083.54,4741.93 3083.05,4742.42 3083.05,4783.05 3098.62,4798.62 3190,4798.62
  Top Layer w20: C127.2@3170,4798.62 R168.2@3215,4798.62
NetC135_1: C135.1 R185.2 U5.12 | length 300.6
  Top Layer w10: C135.1@2780,4971.38 2780,4967.44 2805.28,4942.16 v1@2805.28,4939.92 ; v1(2806.38,4938.82) 2807.93,4938.82 2810.81,4935.94 2811.5,4935.94 2847.32,4900.12 U5.12@2847.32,4741.93
  Bottom Layer w10: R185.2@2780,4971.38 2780,4967.44 2805.28,4942.16 2805.28,4939.92 v1(2806.38,4938.82)
NetC137_1: C137.1 R190.2 U5.15 | length 328.3
  Top Layer w10: C137.1@2643.15,4971.38 2643.15,4967.44 2668.9,4941.69 2668.9,4939.92 v1(2670,4938.82) 2776.46,4832.36 U5.15@2776.46,4741.93
  Bottom Layer w10: R190.2@2643.15,4971.38 2643.15,4967.44 2668.9,4941.69 2668.9,4939.92 v1(2670,4938.82)
NetC138_1: C138.1 R191.2 U5.13 | length 312.8
  Top Layer w10: C138.1@2735,4971.38 2735,4967.44 2763.62,4938.82 v1(2765,4938.82) 2823.7,4880.12 U5.13@2823.7,4741.93
  Bottom Layer w10: R191.2@2735,4971.38 2735,4967.44 2763.62,4938.82 v1(2765,4938.82)
NetC139_1: C139.1 R177.2 U5.8 | length 281.2
  Top Layer w10: U5.8@2941.81,4741.93 v1(2941.81,4938.82) 2941.81,4944.25 2965,4967.44 C139.1@2965,4971.38
  Bottom Layer w10: v1(2941.81,4938.82) 2942.91,4939.92 2942.91,4945.35 2965,4967.44 R177.2@2965,4971.38
NetC140_1: C140.1 R183.2 U5.9 | length 262.3
  Top Layer w10: C140.1@2917.76,4971.38 2917.97,4971.16 v1(2917.97,4938.82) 2917.97,4742.15 U5.9@2918.19,4741.93
  Bottom Layer w10: R183.2@2917.76,4971.38 2917.86,4971.27 2917.86,4938.93 v1(2917.97,4938.82)
NetC141_1: C141.1 R171.2 U5.5 | length 310
  Top Layer w10: U5.5@3012.68,4741.93 3012.68,4880.12 v1(3071.38,4938.82) 3100,4967.44 C141.1@3100,4971.38
  Bottom Layer w10: v1(3071.38,4938.82) 3100,4967.44 R171.2@3100,4971.38
NetC142_1: C142.1 R172.2 U5.6 | length 301.2
  Top Layer w10: U5.6@2989.06,4741.93 2989.06,4901.5 v1(3026.38,4938.82) 3055,4967.44 C142.1@3055,4971.38
  Bottom Layer w10: v1(3026.38,4938.82) 3055,4967.44 R172.2@3055,4971.38
NetC143_1: C143.1 R173.2 U5.7 | length 298.6
  Top Layer w10: U5.7@2965.43,4741.93 2965.43,4926.81 v1(2977.44,4938.82) 2999.25,4960.63 3003.19,4960.63 3010,4967.44 C143.1@3010,4971.38
  Bottom Layer w10: v1(2977.44,4938.82) 2999.25,4960.63 3003.19,4960.63 3010,4967.44 R173.2@3010,4971.38
NetC151_1: C151.1 C152.2 R201.2 U6.3 | length 147.5
  Top Layer w10: U6.3@5577.91,4741.93 5580.98,4745 5580.98,4788.07 5621.22,4828.31 C152.2@5664.37,4828.31
NetC154_2: C154.2 R205.2 U6.11 | length 293.9
  Top Layer w10: C154.2@5335,4971.38 5335,4940.32 5341.69,4933.63 v1(5341.69,4932.07) 5364.93,4908.83 5388.94,4884.83 U6.11@5388.94,4741.93
  Bottom Layer w10: R205.2@5335,4971.38 5335,4940.32 5341.69,4933.63 v1(5341.69,4932.07)
NetC155_2: C155.2 R207.2 U6.10 | length 285.1
  Top Layer w10: C155.2@5380,4971.38 5380,4938.94 v1(5386.87,4932.07) 5412.56,4906.38 U6.10@5412.56,4741.93
  Bottom Layer w10: R207.2@5380,4971.38 5380,4940.49 5386.87,4933.63 v1(5386.87,4932.07)
NetC156_2: C156.2 R208.2 U6.4 | length 316.3
  Top Layer w10: U6.4@5554.29,4741.93 5554.29,4849.05 v1(5635.44,4930.2) 5650,4944.76 C156.2@5650,4971.38
  Bottom Layer w10: v1(5635.44,4930.2) 5650,4944.76 R208.2@5650,4971.38
NetC157_2: C157.2 R211.2 U6.2 | length 188.5
  Top Layer w10: U6.2@5601.54,4741.93 5604.61,4745 5604.61,4776.22 5621.53,4793.15 5691.18,4793.15 5697.99,4786.33 C157.2@5697.99,4783.62
  Top Layer w20: C157.2@5697.99,4788.62 R211.2@5745,4788.62
NetC165_1: C165.1 R228.2 U6.12 | length 300
  Top Layer w10: C165.1@5290,4971.38 v1(5290,4932.07) 5365.31,4856.76 U6.12@5365.31,4741.93
  Bottom Layer w10: v1(5290,4932.07) R228.2@5290,4971.38
NetC167_1: C167.1 R233.2 U6.15 | length 326
  Top Layer w10: C167.1@5155,4971.38 v1(5155,4932.59) 5294.45,4793.15 U6.15@5294.45,4741.93
  Bottom Layer w10: v1(5155,4932.59) R233.2@5155,4971.38
NetC168_1: C168.1 R234.2 U6.13 | length 308.3
  Top Layer w10: C168.1@5245,4971.38 v1(5245,4932.59) 5245,4917.54 5341.69,4820.85 U6.13@5341.69,4741.93
  Bottom Layer w10: v1(5245,4932.59) R234.2@5245,4971.38
NetC169_1: C169.1 R220.2 U6.8 | length 274.9
  Top Layer w10: U6.8@5459.8,4741.93 5459.8,4920 v1(5470,4930.2) C169.1@5470,4971.38
  Bottom Layer w10: v1(5470,4930.2) R220.2@5470,4971.38
NetC170_1: C170.1 R226.2 U6.9 | length 274.3
  Top Layer w10: C170.1@5425,4971.38 v1(5425,4931.18) 5436.18,4920 U6.9@5436.18,4741.93
  Bottom Layer w10: v1(5425,4931.18) R226.2@5425,4971.38
NetC171_1: C171.1 R214.2 U6.5 | length 308.4
  Top Layer w10: U6.5@5530.67,4741.93 5530.67,4872.67 v1(5588.2,4930.2) 5604.49,4946.49 5604.49,4970.87 C171.1@5605,4971.38
  Bottom Layer w10: v1(5588.2,4930.2) 5588.2,4931.75 5602.93,4946.49 5602.93,4969.31 R214.2@5605,4971.38
NetC172_1: C172.1 R215.2 U6.6 | length 297.8
  Top Layer w10: U6.6@5507.05,4741.93 5507.05,4889.88 v1(5547.36,4930.2) 5560,4942.83 C172.1@5560,4971.38
  Bottom Layer w10: v1(5547.36,4930.2) 5560,4942.83 R215.2@5560,4971.38
NetC173_1: C173.1 R216.2 U6.7 | length 288.6
  Top Layer w10: U6.7@5483.43,4741.93 5483.43,4910.32 v1(5503.31,4930.2) 5515,4941.89 C173.1@5515,4971.38
  Bottom Layer w10: v1(5503.31,4930.2) 5515,4941.89 R216.2@5515,4971.38
NetC181_2: C181.2 R244.2 | length 61.5
  Top Layer w25: R244.2@1445,1140.12 1445,1175.81 1462.52,1193.33 C181.2@1463.5,1193.33
NetC186_2: C186.2 D39.1 R245.1
NetC189_1: C189.1 R247.2 | length 75.2
  Top Layer w25: C189.1@2086.5,1205 2087.48,1205 2110,1182.48 R247.2@2110,1140.12
NetC190_1: C190.1 U7.5 | length 80.7
  Top Layer w12: C190.1@1770,216.5 1770,217.48 1806.38,253.86 1806.38,282.03 U7.5@1806.48,282.13
NetC191_2: C191.2 R252.2 | length 89.6
  Top Layer w25: R252.2@1156.5,2776.38 1210.55,2776.38 1235,2751.93 C191.2@1235,2750.94
NetC196_2: C196.2 D44.1 R253.1
NetC199_1: C199.1 R255.2 | length 88
  Top Layer w25: R255.2@1176.5,2090 1182.7,2096.2 1223.68,2096.2 1250,2122.52 C199.1@1250,2123.5
NetC200_1: C200.1 U8.5 | length 104.1
  Top Layer w12: C200.1@231.5,2455 232.48,2455 281.61,2405.87 U8.5@315.2,2405.87
NetC201_2: C201.2 R260.2 | length 65.9
  Top Layer w25: R260.2@3213.05,1096.61 3213.05,1122.6 3240.57,1150.12 C201.2@3241.56,1150.12
NetC206_2: C206.2 D49.1 R261.1
NetC209_1: C209.1 R263.2 | length 103.8
  Top Layer w25: C209.1@3871.5,1150 3872.48,1150 3895,1127.48 R263.2@3895,1056.5
NetC210_1: C210.1 U9.5 | length 98.2
  Top Layer w10: C210.1@3510,196.5 3550.39,196.5 3587.13,233.23 U9.5@3587.13,239.13
NetC211_2: C211.2 R268.2 | length 112.4
  Top Layer w25: C211.2@3961.5,4191.38 3962.48,4191.38 3985,4213.9 R268.2@3985,4293.5
NetC216_2: C216.2 D54.1 R269.1
NetC219_1: C219.1 R271.2 | length 108.8
  Top Layer w25: R271.2@3310,4298.5 3310,4222.52 3332.52,4200 C219.1@3333.5,4200
NetC220_1: C220.1 U10.5 | length 73.3
  Top Layer w12: U10.5@3617.24,5109.8 3617.24,5157.72 3634.53,5175 C220.1@3635.51,5175
NetC221_2: C221.2 R276.2 | length 98.8
  Top Layer w25: C221.2@5441.5,2145 5442.48,2145 5465,2167.52 R276.2@5465,2233.5
NetC226_2: C226.2 D59.1 R277.1
NetC229_1: C229.1 R279.2 | length 113
  Top Layer w25: R279.2@4775,2233.5 4775,2167.52 4807.52,2135 C229.1@4808.5,2135
NetC230_1: C230.1 U11.5 | length 90.9
  Top Layer w12: U11.5@5100,3064.61 5100,3100.06 5138.48,3138.54 C230.1@5139.47,3138.54
NetC231_2: C231.2 R284.2 | length 67.3
  Top Layer w25: C231.2@4946.5,4190 4947.48,4190 4970,4212.52 R284.2@4970,4247.01
NetC236_2: C236.2 D64.1 R285.1
NetC239_1: C239.1 R287.2 | length 65.2
  Top Layer w25: R287.2@4305,4247.01 4305,4207.52 4322.52,4190 C239.1@4323.5,4190
NetC240_1: C240.1 U12.5 | length 100.7
  Top Layer w12: U12.5@4607.52,5109.8 4607.52,5139.61 4629.82,5161.91 4629.82,5182.3 4642.52,5195 C240.1@4643.5,5195
NetD1_2: D1.2 R4.2 | length 100.1
  Top Layer w20: D1.2@1403.54,1560 D1.2@1423.54,1540
  Top Layer w25: R4.2@1331.71,1560 D1.2@1403.54,1560
NetD3_1: D3.1 D4.2 | length 119.5
  Top Layer w100: D3.1@1494.96,1783.23 D4.2@1614.51,1783.23
NetD7_2: D7.2 R42.2 | length 1439.6
  Top Layer w20: v1(2460.75,1199.18) 2519.62,1199.18 R42.2@2520.18,1198.62 ; v2(3655,1478.54) D7.2@3725,1478.54
  Signal Layer 2 w20: v1(2460.75,1199.18) 2604,1342.43 2955.95,1342.43 3092.07,1478.54 v2(3655,1478.54)
NetD9_1: D9.1 D10.2 | length 143
  Top Layer w100: D9.1@3309.96,1854.53 D10.2@3452.95,1854.53
NetD13_2: D13.2 R80.2 | length 182
  Top Layer w25: R80.2@5225.55,1570 5273.63,1570 5335.5,1508.13 5335.5,1506.16 5365.52,1476.14 D13.2@5367.49,1476.14
NetD15_1: D15.1 D16.2 | length 165.7
  Top Layer w50: D15.1@5177.24,1849.53 5187.24,1859.53 5324.69,1859.53 D16.2@5334.69,1869.53
NetD19_2: D19.2 R118.2 | length 135.3
  Top Layer w25: D19.2@1550,2682.52 1645,2777.52 R118.2@1645,2778.5
NetD21_1: D21.1 D22.2 | length 225
  Top Layer w50: D22.2@1870,2674.92 1870,2778.55 1899.29,2807.83 1947.76,2807.83 D21.1@1970,2830.08
NetD25_2: D25.2 R161.2 | length 1121.4
  Top Layer w25: v1(2700,3785) R161.2@2700,3828.5 ; D25.2@3290,2951.46 v1(3290,3015)
  Signal Layer 1 w25: v1(2700,3785) 2700,3605 v1(3290,3015)
NetD27_1: D27.1 D28.2 | length 121.6
  Top Layer w100: D28.2@3520,2757.13 D27.1@3520,2878.7
NetD31_2: D31.2 R204.2 | length 835.1
  Top Layer w20: D31.2@4465,3588.62 4466.97,3588.62 4499.49,3621.14 4499.49,3623.11 4558.75,3682.37 4558.75,3835.31 4663.12,3939.69 R204.2@5063.92,3939.69
NetD33_1: D33.1 D34.2 | length 128.8
  Top Layer w50: D34.2@4465,2889.92 D33.1@4465,3018.7
NetD37_2: D37.2 R244.1 T1.8 | length 241.4
  Top Layer w25: R244.1@1445,1077.13 1445.65,1076.48 1445.65,1036.36 1476.38,1005.63 D37.2@1539.47,1005.63 1540.51,1004.59 1631.38,1004.59 T1.8@1632.42,1003.54
NetD39_2: D39.2 R248.2 T1.4 U7.1
NetD41_1: D41.1 R247.1 T1.5 | length 220.7
  Top Layer w25: T1.5@1926.52,1003.54 D41.1@2002.38,1003.54 ; D41.1@2014.47,1010.63 2080.63,1010.63 2107.85,1037.85 2107.85,1074.98 R247.1@2110,1077.13
NetD42_2: D42.2 R252.1 T2.8 | length 218.3
  Top Layer w25: T2.8@1042.8,2582.05 1041.34,2583.5 1041.34,2678.54 D42.2@1039.88,2680 1051,2691.12 1051,2734.86 1092.52,2776.38 R252.1@1093.5,2776.38
NetD44_2: D44.2 R256.2 T2.4 U8.1
NetD46_1: D46.1 R255.1 T2.5 | length 227.8
  Top Layer w25: T2.5@1042.8,2287.95 1043.84,2286.91 1043.84,2191.04 D46.1@1044.88,2190 1056,2178.88 1056,2146.52 1112.52,2090 R255.1@1113.5,2090
NetD47_2: D47.2 R260.1 T3.8 | length 250.6
  Top Layer w25: R260.1@3213.05,1033.62 3219.25,1027.42 3219.25,984.47 3238.72,965 D47.2@3307.3,965 ; D47.2@3307.3,963.96 3408.54,963.96 T3.8@3409.59,962.91
NetD49_2: D49.2 R264.2 T3.4 U9.1
NetD51_1: D51.1 R263.1 T3.5 | length 204.1
  Top Layer w25: T3.5@3703.68,962.91 3704.73,963.96 D51.1@3802.3,963.96 ; D51.1@3802.3,965 3867.48,965 3895,992.52 R263.1@3895,993.5
NetD52_2: D52.2 R268.1 T4.8 | length 210
  Top Layer w25: T4.8@3788.35,4387.2 3789.39,4386.16 3888.96,4386.16 D52.2@3890,4385.12 3957.36,4385.12 3985,4357.48 R268.1@3985,4356.5
NetD54_2: D54.2 R272.2 T4.4 U10.1
NetD56_1: D56.1 R271.1 T4.5 | length 195.5
  Top Layer w25: R271.1@3310,4361.5 3310,4362.48 3333,4385.48 D56.1@3405,4385.48 3405.86,4386.34 3493.39,4386.34 T4.5@3494.25,4387.2
NetD57_2: D57.2 R276.1 T5.8 | length 210.7
  Top Layer w25: T5.8@5272.05,2332.2 5273.5,2333.66 5368.54,2333.66 D57.2@5370,2335.12 5427.36,2335.12 5465,2297.48 R276.1@5465,2296.5
NetD59_2: D59.2 R280.2 T5.4 U11.1
NetD61_1: D61.1 R279.1 T5.5 | length 218.3
  Top Layer w25: R279.1@4775,2296.5 4775,2297.48 4797.64,2320.12 4880,2320.12 4892.09,2332.2 T5.5@4977.95,2332.2
NetD62_2: D62.2 R284.1 T6.8 | length 227.8
  Top Layer w25: T6.8@4778.03,4387.2 4778.03,4386.59 4779.51,4385.12 4875,4385.12 D62.2@4875,4380.12 4886.12,4369 4911,4369 4962.81,4317.19 4963.8,4317.19 4970,4310.98 R284.1@4970,4310
NetD64_2: D64.2 R288.2 T6.4 U12.1
NetD66_1: D66.1 R287.1 T6.5 | length 210.7
  Top Layer w25: R287.1@4306.48,4311.48 4362.5,4367.5 4388.88,4367.5 D66.1@4400,4378.62 4478.5,4378.62 4483.94,4384.06 T6.5@4483.94,4387.2
NetJ2_1: J2.1 R292.1 | length 200.8
  Top Layer w20: J2.1@2380,5195 2466.38,5108.62 R292.1@2466.38,5030
NetJ2_2: J2.2 U13.1 U13.2 U14.1 U14.2 | length 1342.7
  Top Layer w10: v1(1545,4680.12) 1546.1,4679.02 1548.07,4679.02 1562.72,4664.37 U14.2@1569.45,4664.37 1576.18,4664.37 1585.12,4673.31 1604.8,4673.31 1604.88,4673.39 U14.1@1604.88,4680.12 ; v1(1740,4664.37) U13.2@1774.45,4664.37 1781.18,4664.37 1790.12,4673.31 1809.8,4673.31 1809.88,4673.39 U13.1@1809.88,4680.12
  Top Layer w12: v1(1740,4664.37) 1740,4728.62 1876.38,4865 2235,4865 2280,4910 J2.2@2280,5190
  Signal Layer 2 w10: v1(1545,4680.12) 1574.72,4709.84 1694.53,4709.84 v1(1740,4664.37)
NetJ2_3: J2.3 R293.2 | length 190.2
  Top Layer w12: R293.2@2035,5088.62 R293.2@2035,5092.56 ; R293.2@2036.97,5090.59 2138.52,5192.14 2177.14,5192.14 J2.3@2180,5195
NetQ1_1: Q1.1 R24.1 R27.2 | length 133
  Top Layer w20: Q1.1@722.6,1630.51 724.41,1628.7 724.41,1560 724.41,1504.09 R24.1@728.5,1500
NetQ2_1: Q2.1 R62.1 R65.2 | length 159
  Top Layer w20: R62.1@2460,1573.5 2460.75,1574.25 2540.16,1574.25 R65.2@2540.91,1575 2536.81,1579.09 2536.81,1648.19 Q2.1@2535,1650
NetQ3_1: Q3.1 R100.1 R103.2 | length 597.9
  Top Layer w20: R103.2@4460.63,1550.63 Q3.1@4460.63,1613.31 ; R103.2@4466.54,1545 4467.52,1545 4583.45,1429.07 4737.43,1429.07 4880.31,1286.18 4881.3,1286.18 4890,1277.48 R100.1@4890,1276.5
NetQ4_1: Q4.1 R139.1 R141.2 | length 152.6
  Top Layer w20: R139.1@1615,3545.75 R141.2@1692.6,3545.75 ; Q4.1@1692.6,3617.76 R141.2@1692.6,3545.75 ; R141.2@1695.56,3545.75 R141.2@1692.6,3545.75
NetQ5_1: Q5.1 R182.1 R184.2 | length 174.7
  Top Layer w20: R182.1@3610,3656.5 3610,3740.79 3611.81,3742.6 Q5.1@3612.24,3742.6 3614.06,3744.41 3693.07,3744.41 R184.2@3697.17,3748.5
NetQ6_1: Q6.1 R225.1 R227.2 | length 174.7
  Top Layer w12: R225.1@4682.76,3698.5 4682.76,3699.49 4731.08,3747.81 4742.3,3747.81 4755,3760.51 R227.2@4755,3761.5
  Top Layer w20: R227.2@4755,3761.5 4759.09,3765.59 4825.94,3765.59 Q6.1@4827.76,3767.4
NetR3_1: R3.1 R11.1 | length 45
  Top Layer w20: R3.1@700,643.62 R11.1@745,643.62
NetR9_1: R9.1 R10.1 U1.26 | length 92.3
  Top Layer w15: U1.26@989.04,1027.68 989.61,1028.25 989.61,1076.05 1000,1086.45 v2(1000,1088.78) v2@1000,1090.46
  Top Layer w20: v2@1000,1090.46 v2(1017.65,1108.1)
NetR12_1: R12.1 R13.1 U1.27 | length 91.2
  Top Layer w12: v2@965.94,1089.48 v2(966.46,1090)
  Top Layer w15: U1.27@965.41,1027.68 v2@965.41,1088.95
  Top Layer w20: v2(966.46,1090) 967.16,1090.69 967.16,1105.71 975.79,1114.35 v2(975.79,1115.33)
NetR16_1: R16.1 R17.1 U1.29 | length 91.9
  Top Layer w15: v2(915,1090) 915,1087.67 918.17,1084.5 U1.29@918.17,1027.68
  Top Layer w20: v2(911.47,1116.81) 911.47,1115.83 914.31,1112.99 914.31,1090.69 v2(915,1090)
NetR19_1: R19.1 R26.1 R30.2 | length 92.7
  Bottom Layer w20: R19.1@1115.51,250 1116.26,250.74 1116.26,341.38 R26.1@1117,342.13
NetR20_1: R20.1 R23.1 U1.30 | length 103.1
  Top Layer w15: v2(875.93,1090) 894.55,1071.38 U1.30@894.55,1027.68
  Top Layer w20: v2(854.73,1114.34) 855.43,1113.64 855.43,1111.48 875.93,1090.98 v2(875.93,1090)
NetR29_2: R29.2 TP10.1 | length 59.9
  Top Layer w12: R29.2@1416.23,1340.34 TP10.1@1416.23,1400.26
NetR32_2: R32.2 TP9.1 | length 61.4
  Top Layer w12: R32.2@1333.62,1006.62 1334.84,1007.84 1392.8,1007.84 TP9.1@1394.02,1009.06
NetR41_1: R41.1 R49.1 | length 45
  Top Layer w20: R41.1@2475,593.62 R49.1@2520,593.62
NetR47_1: R47.1 R48.1 U2.26 | length 88.1
  Top Layer w15: U2.26@2772.62,982.05 2773.19,982.62 2773.19,1028.19 2782.31,1037.31 v2(2782.31,1039.65)
  Top Layer w20: v2(2782.31,1039.65) 2783.29,1039.65 2796.74,1053.1 2802.25,1053.1 v2(2802.94,1053.79)
NetR50_1: R50.1 R51.1 U2.27 | length 89.5
  Top Layer w15: U2.27@2749,982.05 2749.04,982.09 2749.04,1040.55 v2(2749.09,1040.6)
  Top Layer w20: v2(2749.09,1040.6) 2749.57,1041.08 2749.57,1070.63 v2(2750.04,1071.1)
NetR54_1: R54.1 R55.1 U2.29 | length 85.9
  Top Layer w15: v2(2701.66,1039.65) v2(2701.66,1039.65) 2701.71,982.09 U2.29@2701.75,982.05
  Top Layer w20: v2(2698.13,1066.46) 2698.13,1065.48 2700.97,1062.64 2700.97,1040.34 v2(2701.66,1039.65)
NetR57_1: R57.1 R64.1 R68.2 | length 92.7
  Bottom Layer w10: R57.1@2810.07,215 R57.1@2813.05,217.99
  Bottom Layer w20: R57.1@2813.05,217.99 R64.1@2813.05,306.5
NetR58_1: R58.1 R61.1 U2.30 | length 99.4
  Top Layer w15: v2(2666.42,1042.03) 2666.42,1039.69 2678.13,1027.99 U2.30@2678.13,982.05
  Top Layer w20: v2(2636.53,1053.21) 2637.22,1052.52 2654.95,1052.52 2665.44,1042.03 v2(2666.42,1042.03)
NetR67_2: R67.2 TP21.1 | length 75.3
  Top Layer w20: TP21.1@3107.91,1269.43 3108.27,1269.07 3108.27,1194.76 R67.2@3108.62,1194.4
NetR70_2: R70.2 TP20.1 | length 61.4
  Top Layer w20: R70.2@3108.62,965 TP20.1@3170,965
NetR79_1: R79.1 R87.1 | length 45
  Top Layer w20: R79.1@4795,603.62 R87.1@4840,603.62
NetR85_1: R85.1 R86.1 U3.26 | length 103.7
  Top Layer w12: v2@5108.62,1061.86 v2(5108.62,1065)
  Top Layer w15: U3.26@5094.57,992.05 5094.57,1047.8 v2@5108.62,1061.86
  Top Layer w20: v2(5108.62,1065) 5108.62,1065.98 5122.11,1079.47 5122.11,1083.31 v2(5122.8,1084.01)
NetR88_1: R88.1 R89.1 U3.27 | length 100.7
  Top Layer w12: U3.27@5070.94,992.05 U3.27@5070.99,992.09 ; v2(5071.04,1065) v2(5071.04,1065)
  Top Layer w15: U3.27@5070.99,992.09 v2(5071.04,1065)
  Top Layer w20: v2(5071.04,1065) 5071.73,1065.69 5071.73,1087.04 5074.86,1090.17 v2(5074.86,1091.15)
NetR92_1: R92.1 R93.1 U3.29 | length 101.3
  Top Layer w12: v2(5023.61,1065) v2@5023.65,1064.95 ; U3.29@5023.65,992.09 U3.29@5023.7,992.05
  Top Layer w15: U3.29@5023.65,992.09 v2@5023.65,1064.95
  Top Layer w20: v2(5020.08,1091.81) 5020.08,1090.83 5022.91,1087.99 5022.91,1065.69 v2(5023.61,1065)
NetR95_1: R95.1 R102.1 R106.2 | length 92.9
  Bottom Layer w10: R102.1@5135,371.38 5135,283.62 R95.1@5138.62,280
NetR96_1: R96.1 R99.1 U3.30 | length 107.8
  Top Layer w12: v2@4984.32,1061.86 v2(4984.32,1065)
  Top Layer w15: v2@4984.32,1061.86 5000.08,1046.1 U3.30@5000.08,992.05
  Top Layer w20: v2(4962.87,1081.46) 4963.56,1080.77 4967.57,1080.77 4983.34,1065 v2(4984.32,1065)
NetR105_2: R105.2 TP31.1 | length 61.4
  Top Layer w20: R105.2@5565,1163.62 TP31.1@5565,1225
NetR108_2: R108.2 TP30.1 | length 61.4
  Top Layer w20: R108.2@5655,1163.62 TP30.1@5655,1225
NetR117_1: R117.1 R125.1 | length 47.2
  Top Layer w20: R125.1@668.62,3428.82 R117.1@668.62,3476.06
NetR123_1: R123.1 R124.1 U4.26 | length 85.1
  Top Layer w15: U4.26@1056.93,3155.43 1106.53,3155.43 1111.02,3150.94 v2(1113.35,3150.94) ; v2@1113.39,3151.12 v2@1115.22,3149.29 ; v2@1135.34,3145 v2(1137.67,3145)
  Top Layer w20: v2@1131.05,3149.29 v2@1135.34,3145
  Top Layer w25: v2@1115.22,3149.29 v2@1131.05,3149.29
NetR126_1: R126.1 R127.1 U4.27 | length 89.3
  Top Layer w15: U4.27@1056.93,3179.06 1057.37,3179.5 1118.47,3179.5 v2(1118.91,3179.94) ; v2@1118.5,3178.96 v2@1118.69,3178.77 ; v2@1143.69,3178.77 v2(1144.86,3177.61)
  Top Layer w20: v2@1118.69,3178.77 v2@1143.69,3178.77
NetR131_1: R131.1 R140.1 R144.2 | length 96.9
  Bottom Layer w10: R131.1@235,3111.38 236.38,3110 R140.1@331.38,3110
NetR132_1: R132.1 R133.1 U4.29 | length 91.4
  Top Layer w12: U4.29@1056.93,3226.3 U4.29@1056.98,3226.35
  Top Layer w15: U4.29@1056.98,3226.35 1057.32,3226.69 1119.61,3226.69 v2(1120,3227.08)
  Top Layer w25: v2(1120,3227.08) 1143.97,3227.08 v2(1146.81,3229.92)
NetR135_1: R135.1 R137.1 U4.30 | length 98
  Top Layer w15: U4.30@1056.93,3249.92 1057.5,3250.49 1090.49,3250.49 1099.99,3259.99 1109.25,3259.99 v2(1118.5,3260)
  Top Layer w25: v2(1109.25,3288.46) 1109.25,3269.25 v2(1118.5,3260)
